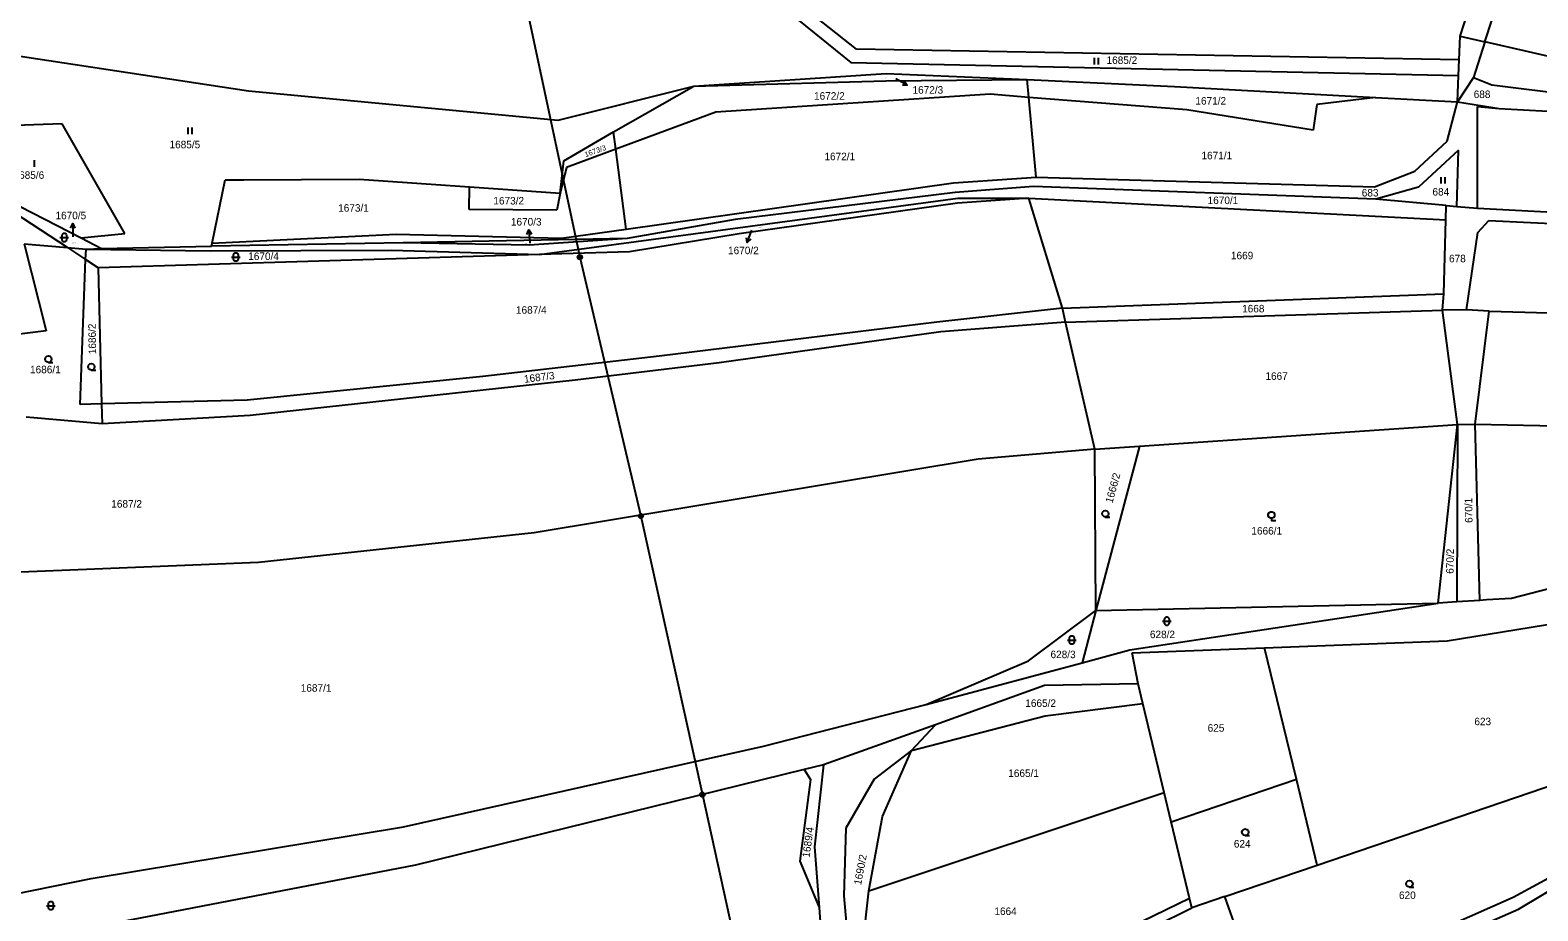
# Model space of a CAD drawing. Extents: x -609861 to -605046, y -1120287 to -1116307.
# Drawn here: x -607842.1 to -607500.4, y -1119513.1 to -1119313.6 of the extents above; entities that cross this region are included whole.
import ezdxf

# ---------------------------------------------------------------- set-up
doc = ezdxf.new("R2010")
doc.units = 0
for name, color, linetype in [('Vrstva 1', 7, 'Continuous'), ('Vrstva 2', 7, 'Continuous'), ('Vrstva 3', 7, 'Continuous'), ('Vrstva 4', 7, 'Continuous'), ('Vrstva 6', 7, 'Continuous'), ('Vrstva 7', 7, 'Continuous')]:
    doc.layers.add(name, color=color, linetype=linetype)

msp = doc.modelspace()

# ---------------------------------------------------------------- linework, layer by layer
at = {"layer": 'Vrstva 1'}
for p, q in [((-607654.83, -1119317.94), (-607684.62, -1119294.06)), ((-607685.58, -1119297.07), (-607656.11, -1119320.92)), ((-607518.01, -1119315.01), (-607514.52, -1119304.17)), ((-607512.42, -1119316.29), (-607508.1, -1119302.87)), ((-607870.82, -1119315.44), (-607792.58, -1119327.38)), ((-607518.24, -1119320.31), (-607518.01, -1119315.01)), ((-607518.01, -1119315.01), (-607512.42, -1119316.29)), ((-607512.42, -1119316.29), (-607515.01, -1119324.35)), ((-607470.96, -1119325.8), (-607512.42, -1119316.29)), ((-607518.24, -1119320.31), (-607654.83, -1119317.94)), ((-607656.11, -1119320.92), (-607518.39, -1119323.88)), ((-607518.39, -1119323.88), (-607518.24, -1119320.31)), ((-607722.43, -1119334), (-607691.67, -1119326.28)), ((-607709.88, -1119336.63), (-607691.67, -1119326.28)), ((-607691.67, -1119326.28), (-607648.12, -1119323.46)), ((-607691.67, -1119326.28), (-607648.15, -1119325.08)), ((-607648.15, -1119325.08), (-607616.1, -1119324.8)), ((-607648.12, -1119323.46), (-607616.1, -1119324.8)), ((-607615.74, -1119328.84), (-607616.1, -1119324.8)), ((-607616.1, -1119324.8), (-607582.77, -1119326.34)), ((-607582.77, -1119326.34), (-607537.24, -1119328.84)), ((-607518.65, -1119329.86), (-607518.39, -1119323.88)), ((-607515.01, -1119324.35), (-607510.86, -1119325.97)), ((-607510.86, -1119325.97), (-607471.83, -1119330.96)), ((-607792.58, -1119327.38), (-607722.43, -1119334)), ((-607624.5, -1119328.14), (-607686.67, -1119332.21)), ((-607615.74, -1119328.84), (-607624.5, -1119328.14)), ((-607614.13, -1119346.9), (-607615.74, -1119328.84)), ((-607579.93, -1119331.7), (-607615.74, -1119328.84)), ((-607537.24, -1119328.84), (-607550.49, -1119330.43)), ((-607537.24, -1119328.84), (-607518.65, -1119329.86)), ((-607520.94, -1119338.78), (-607518.65, -1119329.86)), ((-607518.65, -1119329.86), (-607509.15, -1119331.37)), ((-607686.67, -1119332.21), (-607709.37, -1119340.58)), ((-607551.32, -1119336.29), (-607579.93, -1119331.7)), ((-607550.49, -1119330.43), (-607551.32, -1119336.29)), ((-607514.13, -1119353.94), (-607514.07, -1119330.87)), ((-607514.07, -1119330.87), (-607509.15, -1119331.37)), ((-607509.15, -1119331.37), (-607477.62, -1119333.02)), ((-607834.78, -1119334.81), (-607861.82, -1119335.8)), ((-607820.61, -1119359.64), (-607834.78, -1119334.81)), ((-607721.1, -1119343.18), (-607709.88, -1119336.63)), ((-607709.37, -1119340.58), (-607709.88, -1119336.63)), ((-607528.29, -1119345.56), (-607520.94, -1119338.78)), ((-607721.93, -1119350.51), (-607721.1, -1119343.18)), ((-607709.37, -1119340.58), (-607720.51, -1119344.69)), ((-607707.02, -1119358.66), (-607709.37, -1119340.58)), ((-607518.43, -1119340.81), (-607527.43, -1119349.19)), ((-607518.75, -1119353.58), (-607518.43, -1119340.81)), ((-607860.62, -1119345.14), (-607830.5, -1119360.68)), ((-607833.57, -1119362.87), (-607860.62, -1119345.14)), ((-607720.51, -1119344.69), (-607721.93, -1119350.51)), ((-607632.81, -1119348.22), (-607614.13, -1119346.9)), ((-607614.13, -1119346.9), (-607537.45, -1119349.09)), ((-607537.45, -1119349.09), (-607528.29, -1119345.56)), ((-607800.81, -1119361.9), (-607797.89, -1119347.5)), ((-607797.89, -1119347.5), (-607793.64, -1119347.48)), ((-607793.64, -1119347.48), (-607767.52, -1119347.33)), ((-607767.52, -1119347.33), (-607742.51, -1119349.07)), ((-607742.61, -1119354.25), (-607742.51, -1119349.07)), ((-607742.51, -1119349.07), (-607721.93, -1119350.51)), ((-607721.93, -1119350.51), (-607722.71, -1119354.37)), ((-607707.02, -1119358.66), (-607632.81, -1119348.22)), ((-607632.45, -1119350.41), (-607682.31, -1119356.52)), ((-607614.72, -1119349.02), (-607632.45, -1119350.41)), ((-607537.16, -1119351.93), (-607614.72, -1119349.02)), ((-607527.43, -1119349.19), (-607537.16, -1119351.93)), ((-607631.92, -1119352.84), (-607681.41, -1119359.74)), ((-607674.95, -1119357.49), (-607631.87, -1119351.68)), ((-607615.79, -1119351.66), (-607631.92, -1119352.84)), ((-607631.87, -1119351.68), (-607615.79, -1119351.66)), ((-607608.14, -1119376.59), (-607615.79, -1119351.66)), ((-607615.79, -1119351.66), (-607521.26, -1119356.56)), ((-607521.17, -1119353.36), (-607537.16, -1119351.93)), ((-607521.26, -1119356.56), (-607521.17, -1119353.36)), ((-607521.17, -1119353.36), (-607518.75, -1119353.58)), ((-607518.75, -1119353.58), (-607514.13, -1119353.94)), ((-607514.13, -1119353.94), (-607470.27, -1119356.17)), ((-607722.71, -1119354.37), (-607742.61, -1119354.25)), ((-607726.67, -1119364.41), (-607674.95, -1119357.49)), ((-607682.31, -1119356.52), (-607706.76, -1119360.81)), ((-607521.71, -1119373.33), (-607521.26, -1119356.56)), ((-607514.02, -1119359.44), (-607511.49, -1119356.76)), ((-607511.49, -1119356.76), (-607470.26, -1119358.6)), ((-607830.5, -1119360.68), (-607820.61, -1119359.64)), ((-607830.5, -1119360.68), (-607825.9, -1119363.05)), ((-607800.81, -1119361.9), (-607759.13, -1119359.84)), ((-607759.13, -1119359.84), (-607721.67, -1119360.71)), ((-607706.76, -1119360.81), (-607757.55, -1119361.76)), ((-607706.76, -1119360.81), (-607729, -1119362.34)), ((-607721.67, -1119360.71), (-607707.02, -1119358.66)), ((-607681.41, -1119359.74), (-607706.22, -1119363.79)), ((-607516.55, -1119376.93), (-607514.02, -1119359.44)), ((-607843.37, -1119362.03), (-607838.43, -1119381.69)), ((-607843.37, -1119362.03), (-607833.57, -1119362.87)), ((-607833.57, -1119362.87), (-607829.39, -1119363.23)), ((-607829.48, -1119365.56), (-607829.39, -1119363.23)), ((-607829.39, -1119363.23), (-607825.9, -1119363.05)), ((-607829.39, -1119363.23), (-607801.28, -1119363.6)), ((-607825.9, -1119363.05), (-607800.95, -1119362.58)), ((-607801.28, -1119363.6), (-607760.19, -1119363.45)), ((-607757.55, -1119361.76), (-607800.95, -1119362.58)), ((-607800.95, -1119362.58), (-607800.81, -1119361.9)), ((-607760.19, -1119363.45), (-607726.67, -1119364.41)), ((-607729, -1119362.34), (-607757.55, -1119361.76)), ((-607706.22, -1119363.79), (-607726.67, -1119364.41)), ((-607830.68, -1119398.39), (-607829.48, -1119365.56)), ((-607826.62, -1119367.43), (-607829.48, -1119365.56)), ((-607726.67, -1119364.41), (-607826.62, -1119367.43)), ((-607826.62, -1119367.43), (-607825.88, -1119398.26)), ((-607608.14, -1119376.59), (-607521.71, -1119373.33)), ((-607522, -1119377.04), (-607521.71, -1119373.33)), ((-607608.14, -1119376.59), (-607636.64, -1119379.72)), ((-607607.45, -1119379.72), (-607608.14, -1119376.59)), ((-607607.45, -1119379.72), (-607522, -1119377.04)), ((-607516.55, -1119376.93), (-607522, -1119377.04)), ((-607511.48, -1119377.28), (-607516.55, -1119376.93)), ((-607514.62, -1119402.89), (-607511.48, -1119377.28)), ((-607511.48, -1119377.28), (-607468.99, -1119378.51)), ((-607636.64, -1119379.72), (-607699.53, -1119387.46)), ((-607607.45, -1119379.72), (-607635.72, -1119381.98)), ((-607600.78, -1119408.49), (-607607.45, -1119379.72)), ((-607838.43, -1119381.69), (-607848.73, -1119382.98)), ((-607635.72, -1119381.98), (-607685.94, -1119388.94)), ((-607699.53, -1119387.46), (-607739.45, -1119392.03)), ((-607685.94, -1119388.94), (-607718.57, -1119392.91)), ((-607739.45, -1119392.03), (-607792.9, -1119397.4)), ((-607718.57, -1119392.91), (-607792.19, -1119400.86)), ((-607825.88, -1119398.26), (-607830.68, -1119398.39)), ((-607792.9, -1119397.4), (-607825.88, -1119398.26)), ((-607825.88, -1119398.26), (-607825.77, -1119402.78)), ((-607825.77, -1119402.78), (-607842.98, -1119401.3)), ((-607792.19, -1119400.86), (-607825.77, -1119402.78)), ((-607590.71, -1119407.81), (-607518.62, -1119402.91)), ((-607523.02, -1119443.42), (-607518.62, -1119402.91)), ((-607518.62, -1119402.91), (-607518.78, -1119443.13)), ((-607518.62, -1119402.91), (-607514.62, -1119402.89)), ((-607513.6, -1119442.77), (-607514.62, -1119402.89)), ((-607514.62, -1119402.89), (-607465.63, -1119403.81)), ((-607600.78, -1119408.49), (-607627.21, -1119410.78)), ((-607600.78, -1119408.49), (-607590.71, -1119407.81)), ((-607600.54, -1119445.06), (-607600.78, -1119408.49)), ((-607590.71, -1119407.81), (-607600.54, -1119445.06)), ((-607627.21, -1119410.78), (-607727.88, -1119427.47)), ((-607727.88, -1119427.47), (-607790.34, -1119434.22)), ((-607790.34, -1119434.22), (-607864.61, -1119437.2)), ((-607493.27, -1119438.96), (-607506.36, -1119442.36)), ((-607513.6, -1119442.77), (-607518.78, -1119443.13)), ((-607512.06, -1119442.68), (-607513.6, -1119442.77)), ((-607506.36, -1119442.36), (-607512.06, -1119442.68)), ((-607615.81, -1119456.48), (-607600.54, -1119445.06)), ((-607600.54, -1119445.06), (-607603.66, -1119456.88)), ((-607600.54, -1119445.06), (-607523.02, -1119443.42)), ((-607592.89, -1119454.01), (-607523.02, -1119443.42)), ((-607518.78, -1119443.13), (-607523.02, -1119443.42)), ((-607520.97, -1119451.93), (-607479.97, -1119445.26)), ((-607562.38, -1119453.5), (-607520.97, -1119451.93)), ((-607639.04, -1119466.34), (-607615.81, -1119456.48)), ((-607603.66, -1119456.88), (-607592.89, -1119454.01)), ((-607592.36, -1119454.64), (-607562.38, -1119453.5)), ((-607590.96, -1119461.67), (-607592.36, -1119454.64)), ((-607555.09, -1119483.26), (-607562.38, -1119453.5)), ((-607639.04, -1119466.34), (-607603.66, -1119456.88)), ((-607612.2, -1119462.03), (-607636.9, -1119470.98)), ((-607590.96, -1119461.67), (-607612.2, -1119462.03)), ((-607589.9, -1119466.11), (-607590.96, -1119461.67)), ((-607675.85, -1119475.76), (-607639.04, -1119466.34)), ((-607612.09, -1119468.91), (-607589.9, -1119466.11)), ((-607585.07, -1119486.27), (-607589.9, -1119466.11)), ((-607642.38, -1119476.75), (-607612.09, -1119468.91)), ((-607636.9, -1119470.98), (-607662.31, -1119480)), ((-607642.38, -1119476.75), (-607636.9, -1119470.98)), ((-607757.43, -1119494.08), (-607675.85, -1119475.76)), ((-607642.38, -1119476.75), (-607650.79, -1119483.27)), ((-607648.89, -1119491.76), (-607642.38, -1119476.75)), ((-607662.31, -1119480), (-607666.65, -1119481.07)), ((-607662.31, -1119480), (-607664.35, -1119498.63)), ((-607550.42, -1119502.71), (-607475.55, -1119477.21)), ((-607666.65, -1119481.07), (-607754.71, -1119502.76)), ((-607665.26, -1119483.35), (-607667.62, -1119501.83)), ((-607666.65, -1119481.07), (-607665.26, -1119483.35)), ((-607650.79, -1119483.27), (-607657.23, -1119494.39)), ((-607583.48, -1119492.94), (-607555.09, -1119483.26)), ((-607550.42, -1119502.71), (-607555.09, -1119483.26)), ((-607652.04, -1119508.57), (-607588.07, -1119487.27)), ((-607588.07, -1119487.27), (-607585.07, -1119486.27)), ((-607583.48, -1119492.94), (-607585.07, -1119486.27)), ((-607828.19, -1119505.73), (-607757.43, -1119494.08)), ((-607652.04, -1119508.57), (-607648.89, -1119491.76)), ((-607579.33, -1119510.25), (-607583.48, -1119492.94)), ((-607657.23, -1119494.39), (-607657.66, -1119509.69)), ((-607664.35, -1119498.63), (-607663.29, -1119512.34)), ((-607754.71, -1119502.76), (-607825.32, -1119516.35)), ((-607667.62, -1119501.83), (-607663.29, -1119512.34)), ((-607571.35, -1119509.84), (-607550.42, -1119502.71)), ((-607490.73, -1119501.75), (-607505.99, -1119510.07)), ((-607856.4, -1119511.53), (-607828.19, -1119505.73)), ((-607504.84, -1119512.7), (-607493.92, -1119506.24)), ((-607657.66, -1119509.69), (-607656.37, -1119524.99)), ((-607655.83, -1119542.55), (-607652.04, -1119508.57)), ((-607598.17, -1119519.35), (-607579.33, -1119510.25)), ((-607578.82, -1119512.39), (-607579.33, -1119510.25)), ((-607571.35, -1119509.84), (-607578.82, -1119512.39)), ((-607570.44, -1119512.39), (-607571.35, -1119509.84)), ((-607505.99, -1119510.07), (-607562.44, -1119534.97)), ((-607663.29, -1119512.34), (-607662.48, -1119522.89)), ((-607596.96, -1119521.36), (-607578.82, -1119512.39)), ((-607562.44, -1119534.97), (-607570.44, -1119512.39)), ((-607561.4, -1119537.44), (-607504.84, -1119512.7))]:
    msp.add_line(p, q, dxfattribs=at)
at = {"layer": 'Vrstva 3'}
for p, q in [((-607600.98, -1119319.89), (-607600.98, -1119321.39)), ((-607599.98, -1119321.39), (-607599.98, -1119319.89)), ((-607806.35, -1119335.64), (-607806.35, -1119337.14)), ((-607805.35, -1119337.14), (-607805.35, -1119335.64)), ((-607841.08, -1119344.58), (-607841.08, -1119343.08)), ((-607522.43, -1119346.88), (-607522.43, -1119348.38)), ((-607521.43, -1119348.38), (-607521.43, -1119346.88))]:
    msp.add_line(p, q, dxfattribs=at)
for points in [[(-607835.33, -1119360.6), (-607834.06, -1119360.6), (-607833.33, -1119360.6)], [(-607796.46, -1119365), (-607795.19, -1119365), (-607794.46, -1119365)], [(-607837.91, -1119388.86), (-607838.29, -1119388.76), (-607838.56, -1119388.49), (-607838.66, -1119388.12), (-607838.56, -1119387.75), (-607838.29, -1119387.48), (-607837.92, -1119387.38), (-607837.55, -1119387.48), (-607837.28, -1119387.75), (-607837.18, -1119388.13), (-607837.28, -1119388.51), (-607837.55, -1119388.78), (-607837.93, -1119388.88), (-607836.93, -1119388.88)], [(-607828.18, -1119390.6), (-607828.56, -1119390.5), (-607828.83, -1119390.23), (-607828.93, -1119389.86), (-607828.83, -1119389.49), (-607828.56, -1119389.22), (-607828.19, -1119389.12), (-607827.82, -1119389.22), (-607827.55, -1119389.49), (-607827.45, -1119389.87), (-607827.55, -1119390.25), (-607827.82, -1119390.52), (-607828.2, -1119390.62), (-607827.2, -1119390.62)], [(-607598.42, -1119423.87), (-607598.8, -1119423.77), (-607599.07, -1119423.5), (-607599.17, -1119423.13), (-607599.07, -1119422.76), (-607598.8, -1119422.49), (-607598.43, -1119422.39), (-607598.06, -1119422.49), (-607597.79, -1119422.76), (-607597.69, -1119423.14), (-607597.79, -1119423.52), (-607598.06, -1119423.79), (-607598.44, -1119423.89), (-607597.44, -1119423.89)], [(-607560.79, -1119424.16), (-607560.98, -1119424.16), (-607561.32, -1119423.97), (-607561.51, -1119423.63), (-607561.51, -1119423.24), (-607561.32, -1119422.9), (-607560.98, -1119422.71), (-607560.59, -1119422.71), (-607560.25, -1119422.9), (-607560.06, -1119423.24), (-607560.06, -1119423.63), (-607560.25, -1119423.97), (-607560.59, -1119424.16), (-607560.78, -1119424.16), (-607560.78, -1119424.69), (-607559.78, -1119424.69)], [(-607585.49, -1119447.48), (-607584.22, -1119447.48), (-607583.49, -1119447.48)], [(-607607.02, -1119451.75), (-607605.75, -1119451.75), (-607605.02, -1119451.75)], [(-607566.72, -1119496.03), (-607567.1, -1119495.93), (-607567.37, -1119495.66), (-607567.47, -1119495.29), (-607567.37, -1119494.92), (-607567.1, -1119494.65), (-607566.73, -1119494.55), (-607566.36, -1119494.65), (-607566.09, -1119494.92), (-607565.99, -1119495.3), (-607566.09, -1119495.68), (-607566.36, -1119495.95), (-607566.74, -1119496.05), (-607565.74, -1119496.05)], [(-607529.51, -1119507.71), (-607529.89, -1119507.61), (-607530.16, -1119507.34), (-607530.26, -1119506.97), (-607530.16, -1119506.6), (-607529.89, -1119506.33), (-607529.52, -1119506.23), (-607529.15, -1119506.33), (-607528.88, -1119506.6), (-607528.78, -1119506.98), (-607528.88, -1119507.36), (-607529.15, -1119507.63), (-607529.53, -1119507.73), (-607528.53, -1119507.73)], [(-607838.38, -1119511.92), (-607837.11, -1119511.92), (-607836.38, -1119511.92)]]:
    msp.add_lwpolyline(points, dxfattribs=at)
for points in [[(-607834.83, -1119360.1), (-607834.73, -1119359.81), (-607834.48, -1119359.63), (-607834.17, -1119359.63), (-607833.92, -1119359.81), (-607833.82, -1119360.1), (-607833.82, -1119361.1), (-607833.92, -1119361.39), (-607834.17, -1119361.57), (-607834.48, -1119361.57), (-607834.73, -1119361.39), (-607834.83, -1119361.1)], [(-607795.96, -1119364.5), (-607795.86, -1119364.21), (-607795.61, -1119364.03), (-607795.3, -1119364.03), (-607795.05, -1119364.21), (-607794.95, -1119364.5), (-607794.95, -1119365.5), (-607795.05, -1119365.79), (-607795.3, -1119365.97), (-607795.61, -1119365.97), (-607795.86, -1119365.79), (-607795.96, -1119365.5)], [(-607584.99, -1119446.98), (-607584.89, -1119446.69), (-607584.64, -1119446.51), (-607584.33, -1119446.51), (-607584.08, -1119446.69), (-607583.98, -1119446.98), (-607583.98, -1119447.98), (-607584.08, -1119448.27), (-607584.33, -1119448.45), (-607584.64, -1119448.45), (-607584.89, -1119448.27), (-607584.99, -1119447.98)], [(-607606.52, -1119451.25), (-607606.42, -1119450.96), (-607606.17, -1119450.78), (-607605.86, -1119450.78), (-607605.61, -1119450.96), (-607605.51, -1119451.25), (-607605.51, -1119452.25), (-607605.61, -1119452.54), (-607605.86, -1119452.72), (-607606.17, -1119452.72), (-607606.42, -1119452.54), (-607606.52, -1119452.25)], [(-607837.88, -1119511.42), (-607837.78, -1119511.13), (-607837.53, -1119510.95), (-607837.22, -1119510.95), (-607836.97, -1119511.13), (-607836.87, -1119511.42), (-607836.87, -1119512.42), (-607836.97, -1119512.71), (-607837.22, -1119512.89), (-607837.53, -1119512.89), (-607837.78, -1119512.71), (-607837.88, -1119512.42)]]:
    msp.add_lwpolyline(points, close=True, dxfattribs=at)
at = {"layer": 'Vrstva 4'}
for p, q in [((-607515.01, -1119324.35), (-607518.65, -1119329.86)), ((-607833.57, -1119362.87), (-607829.48, -1119365.56)), ((-607518.62, -1119402.91), (-607522, -1119377.04))]:
    msp.add_line(p, q, dxfattribs=at)
at = {"layer": 'Vrstva 6'}
for p, q in [((-607736.34, -1119276.73), (-607717.49, -1119365.03)), ((-607717.49, -1119365.03), (-607703.67, -1119423.66)), ((-607703.67, -1119423.66), (-607689.72, -1119486.78)), ((-607689.72, -1119486.78), (-607674.61, -1119555.38))]:
    msp.add_line(p, q, dxfattribs=at)
for points in [[(-607717.64, -1119364.55), (-607717.33, -1119364.55), (-607717.08, -1119364.73), (-607716.98, -1119365.02), (-607717.08, -1119365.31), (-607717.33, -1119365.49), (-607717.64, -1119365.49), (-607717.89, -1119365.31), (-607717.99, -1119365.02), (-607717.89, -1119364.73), (-607717.64, -1119364.55), (-607717.61, -1119364.59), (-607717.37, -1119364.59), (-607717.21, -1119364.67), (-607717.77, -1119364.67), (-607717.85, -1119364.75), (-607717.13, -1119364.75), (-607717.13, -1119364.83), (-607717.85, -1119364.83), (-607717.89, -1119364.91), (-607717.09, -1119364.91), (-607717.05, -1119364.99), (-607717.93, -1119364.99), (-607717.93, -1119365.07), (-607717.05, -1119365.07), (-607717.08, -1119365.15), (-607717.89, -1119365.15), (-607717.88, -1119365.23), (-607717.07, -1119365.23), (-607717.12, -1119365.31), (-607717.84, -1119365.31), (-607717.76, -1119365.39), (-607717.2, -1119365.39), (-607717.31, -1119365.47), (-607717.65, -1119365.47)], [(-607703.82, -1119423.18), (-607703.51, -1119423.18), (-607703.26, -1119423.36), (-607703.16, -1119423.65), (-607703.26, -1119423.94), (-607703.51, -1119424.12), (-607703.82, -1119424.12), (-607704.07, -1119423.94), (-607704.17, -1119423.65), (-607704.07, -1119423.36), (-607703.82, -1119423.18), (-607703.79, -1119423.22), (-607703.55, -1119423.22), (-607703.39, -1119423.3), (-607703.95, -1119423.3), (-607704.03, -1119423.38), (-607703.31, -1119423.38), (-607703.31, -1119423.46), (-607704.03, -1119423.46), (-607704.07, -1119423.54), (-607703.27, -1119423.54), (-607703.23, -1119423.62), (-607704.11, -1119423.62), (-607704.11, -1119423.7), (-607703.23, -1119423.7), (-607703.26, -1119423.78), (-607704.07, -1119423.78), (-607704.06, -1119423.86), (-607703.25, -1119423.86), (-607703.3, -1119423.94), (-607704.02, -1119423.94), (-607703.94, -1119424.02), (-607703.38, -1119424.02), (-607703.49, -1119424.1), (-607703.83, -1119424.1)], [(-607689.87, -1119486.3), (-607689.56, -1119486.3), (-607689.31, -1119486.48), (-607689.21, -1119486.77), (-607689.31, -1119487.06), (-607689.56, -1119487.24), (-607689.87, -1119487.24), (-607690.12, -1119487.06), (-607690.22, -1119486.77), (-607690.12, -1119486.48), (-607689.87, -1119486.3), (-607689.84, -1119486.34), (-607689.6, -1119486.34), (-607689.44, -1119486.42), (-607690, -1119486.42), (-607690.08, -1119486.5), (-607689.36, -1119486.5), (-607689.36, -1119486.58), (-607690.08, -1119486.58), (-607690.12, -1119486.66), (-607689.32, -1119486.66), (-607689.28, -1119486.74), (-607690.16, -1119486.74), (-607690.16, -1119486.82), (-607689.28, -1119486.82), (-607689.31, -1119486.9), (-607690.12, -1119486.9), (-607690.11, -1119486.98), (-607689.3, -1119486.98), (-607689.35, -1119487.06), (-607690.07, -1119487.06), (-607689.99, -1119487.14), (-607689.43, -1119487.14), (-607689.54, -1119487.22), (-607689.88, -1119487.22)]]:
    msp.add_lwpolyline(points, dxfattribs=at)
at = {"layer": 'Vrstva 7'}
for p, q in [((-607643.295, -1119326.092), (-607645.92, -1119324.64)), ((-607832.4, -1119357.44), (-607832.4, -1119360.44)), ((-607729.072, -1119358.863), (-607728.79, -1119361.85)), ((-607679.608, -1119361.732), (-607678.51, -1119358.94))]:
    msp.add_line(p, q, dxfattribs=at)
for points in [[(-607643.928, -1119325.171), (-607643.295, -1119326.092), (-607644.412, -1119326.046)], [(-607832.9, -1119358.44), (-607832.4, -1119357.44), (-607831.9, -1119358.44)], [(-607729.476, -1119359.906), (-607729.072, -1119358.863), (-607728.48, -1119359.812)], [(-607678.776, -1119360.984), (-607679.608, -1119361.732), (-607679.707, -1119360.618)]]:
    msp.add_lwpolyline(points, dxfattribs=at)

# ---------------------------------------------------------------- texts
at = {"layer": 'Vrstva 2'}
for s, height, p in [('1685/2', 1.7, (-607598.147, -1119321.27)), ('1672/3', 0.2, (-607648.334, -1119324.55)), ('1672/2', 1.7, (-607664.427, -1119329.36)), ('1671/2', 1.7, (-607578.017, -1119330.48)), ('688', 1.7, (-607514.953, -1119328.99)), ('1685/5', 1.7, (-607810.467, -1119340.37)), ('1672/1', 1.7, (-607662.067, -1119343.07)), ('1671/1', 1.7, (-607576.637, -1119342.86)), ('1685/6', 1.7, (-607845.817, -1119347.29)), ('683', 1.7, (-607540.323, -1119351.29)), ('684', 1.7, (-607524.303, -1119351.08)), ('1673/1', 1.7, (-607772.257, -1119354.73)), ('1673/2', 1.7, (-607737.087, -1119353.1)), ('1670/1', 1.7, (-607575.247, -1119353.01)), ('1670/5', 0.2, (-607832.534, -1119361.97)), ('1670/4', 1.7, (-607792.637, -1119365.67)), ('1670/3', 0.2, (-607730.324, -1119362.01)), ('1669', 1.7, (-607569.957, -1119365.51)), ('678', 1.7, (-607520.543, -1119366.19)), ('1687/4', 1.7, (-607731.967, -1119377.84)), ('1668', 1.7, (-607567.427, -1119377.54)), ('1686/1', 1.7, (-607842.077, -1119391.33)), ('1667', 1.7, (-607562.147, -1119392.82)), ('1687/2', 1.7, (-607823.667, -1119421.76)), ('1666/1', 1.7, (-607565.327, -1119427.86)), ('628/2', 1.7, (-607588.323, -1119451.33)), ('628/3', 1.7, (-607610.843, -1119455.86)), ('1687/1', 1.7, (-607780.737, -1119463.45)), ('1665/2', 1.7, (-607616.557, -1119466.9)), ('623', 1.7, (-607514.803, -1119471.05)), ('625', 1.7, (-607575.243, -1119472.51)), ('1665/1', 1.7, (-607620.417, -1119482.77)), ('624', 1.7, (-607569.303, -1119498.76)), ('620', 1.7, (-607531.883, -1119510.41)), ('1664', 1.7, (-607623.557, -1119514.03))]:
    msp.add_text(s, height=height, dxfattribs=at).set_placement(p)
for s, height, rotation, p in [('1673/3', 1.2, 19.82434, (-607716.179, -1119342.406)), ('1670/2', 0.2, 7.21927, (-607677.064, -1119358.434)), ('1686/2', 1.7, 90.9284, (-607827.086, -1119387.007)), ('1687/3', 1.7, 7.21927, (-607730.04, -1119393.511)), ('1666/2', 1.7, 74.7137, (-607596.816, -1119420.871)), ('670/1', 1.7, 90.9284, (-607515.206, -1119425.213)), ('670/2', 1.7, 89.09494, (-607519.524, -1119436.763)), ('1689/4', 1.7, 81.87567, (-607665.455, -1119501.111)), ('1690/2', 1.7, 79.18277, (-607653.766, -1119507.324))]:
    msp.add_text(s, height=height, rotation=rotation, dxfattribs=at).set_placement(p)
at = {"layer": 'Vrstva 7'}
for s, p in [('1672/3', (-607642.117, -1119328)), ('1670/5', (-607836.308, -1119356.44)), ('1670/3', (-607733.118, -1119357.87)), ('1670/2', (-607683.915, -1119364.36))]:
    msp.add_text(s, height=1.7, dxfattribs=at).set_placement(p)

doc.saveas('drawing.dxf')
